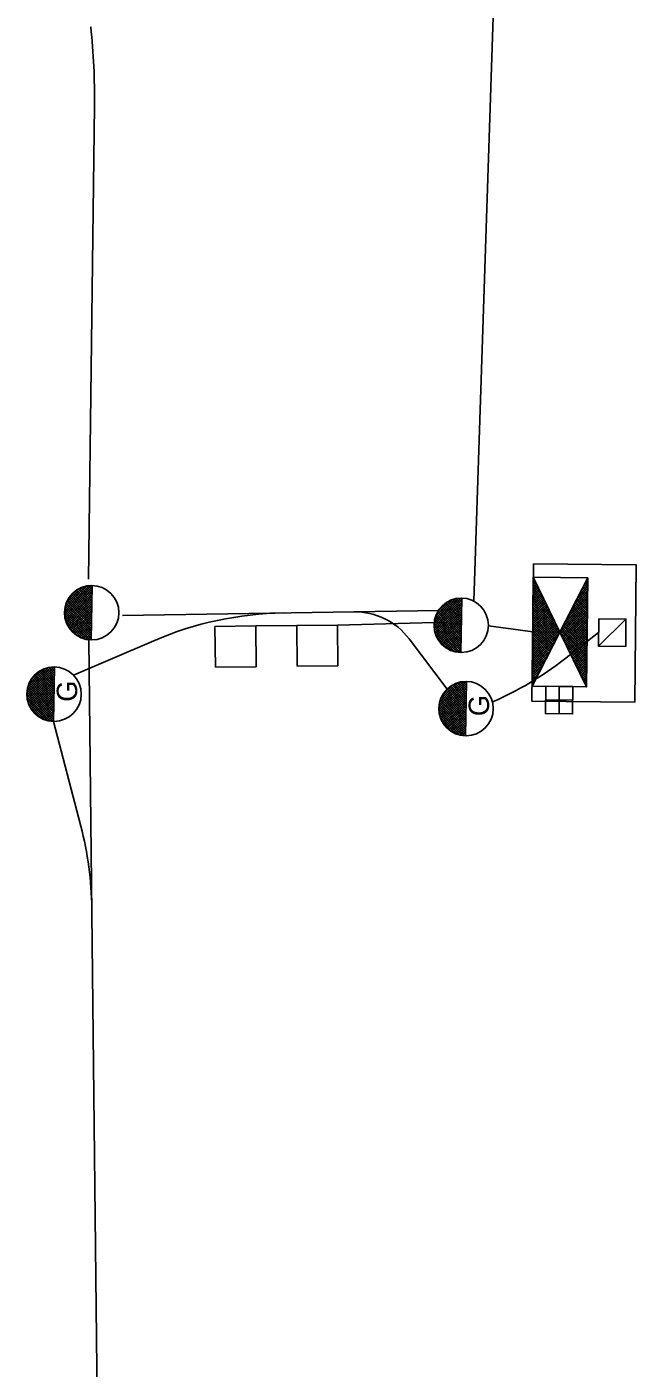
# Model space of a CAD drawing. Extents: x 584850 to 602551, y 145475 to 158627.
# Drawn here: x 585433.1 to 585522.7, y 152144.7 to 152341.8 of the extents above; entities that cross this region are included whole.
import ezdxf

# ---------------------------------------------------------------- set-up
doc = ezdxf.new("R2010")
doc.units = 0
doc.layers.add('Default', color=7, linetype='Continuous')

msp = doc.modelspace()

# ---------------------------------------------------------------- linework, layer by layer
at = {"layer": 'Default'}
for p, q in [((585498.86, 152257.42), (585505.09, 152448.58)), ((585442.22, 152260.66), (585443.08, 152330.19)), ((585442.66, 152259.72), (585438.68, 152255.88)), ((585442.29, 152259.7), (585438.71, 152256.26)), ((585441.88, 152259.64), (585438.77, 152256.64)), ((585441.62, 152259.58), (585442.72, 152258.44)), ((585441.9, 152259.64), (585442.72, 152258.78)), ((585442.18, 152259.69), (585442.73, 152259.12)), ((585442.5, 152259.71), (585442.74, 152259.46)), ((585442.59, 152251.73), (585442.74, 152259.73)), ((585442.7, 152259.73), (585442.74, 152259.68)), ((585508.06, 152259.94), (585507.56, 152259.45)), ((585508.17, 152259.71), (585507.56, 152259.11)), ((585507.73, 152260.62), (585507.57, 152260.47)), ((585507.84, 152260.39), (585507.57, 152260.13)), ((585508.17, 152259.71), (585507.57, 152260.32)), ((585507.95, 152260.16), (585507.57, 152259.79)), ((585508.5, 152259.03), (585507.57, 152259.98)), ((585508.84, 152258.34), (585507.57, 152259.64)), ((585507.62, 152260.85), (585507.58, 152260.81)), ((585507.84, 152260.39), (585507.58, 152260.66)), ((585515.57, 152259.89), (585514.61, 152258.96)), ((585515.57, 152260.23), (585514.96, 152259.63)), ((585515.56, 152259.02), (585514.96, 152259.63)), ((585515.56, 152259.36), (585515.08, 152259.86)), ((585515.57, 152259.7), (585515.19, 152260.08)), ((585515.58, 152260.57), (585515.31, 152260.31)), ((585515.57, 152260.04), (585515.31, 152260.31)), ((585515.58, 152260.38), (585515.42, 152260.53)), ((585515.58, 152260.72), (585515.54, 152260.76)), ((585442.74, 152259.46), (585438.68, 152255.56)), ((585442.73, 152259.12), (585438.7, 152255.24)), ((585442.72, 152258.78), (585438.75, 152254.96)), ((585442.72, 152258.44), (585438.81, 152254.68)), ((585442.71, 152258.11), (585438.9, 152254.43)), ((585441.42, 152259.53), (585438.93, 152257.13)), ((585442.7, 152257.77), (585438.99, 152254.19)), ((585439.17, 152257.63), (585442.63, 152254.03)), ((585440.8, 152259.27), (585439.22, 152257.74)), ((585439.28, 152257.86), (585442.64, 152254.37)), ((585439.43, 152258.06), (585442.65, 152254.71)), ((585439.57, 152258.25), (585442.65, 152255.05)), ((585439.72, 152258.44), (585442.66, 152255.39)), ((585439.9, 152258.6), (585442.67, 152255.73)), ((585440.08, 152258.76), (585442.67, 152256.07)), ((585440.26, 152258.92), (585442.68, 152256.41)), ((585440.46, 152259.05), (585442.69, 152256.75)), ((585440.67, 152259.19), (585442.69, 152257.09)), ((585440.89, 152259.3), (585442.7, 152257.43)), ((585441.13, 152259.41), (585442.7, 152257.77)), ((585441.36, 152259.51), (585442.71, 152258.11)), ((585496.99, 152257.87), (585493, 152254.04)), ((585497.06, 152257.61), (585493.01, 152253.71)), ((585496.62, 152257.85), (585493.04, 152254.41)), ((585496.21, 152257.79), (585493.1, 152254.79)), ((585495.75, 152257.68), (585493.26, 152255.28)), ((585495.69, 152257.66), (585497.04, 152256.26)), ((585495.95, 152257.73), (585497.04, 152256.6)), ((585496.22, 152257.79), (585497.05, 152256.93)), ((585496.51, 152257.84), (585497.06, 152257.27)), ((585496.82, 152257.86), (585497.06, 152257.61)), ((585496.92, 152249.88), (585497.07, 152257.88)), ((585497.02, 152257.88), (585497.07, 152257.83)), ((585508.95, 152258.12), (585507.53, 152256.74)), ((585509.06, 152257.89), (585507.53, 152256.4)), ((585509.17, 152257.66), (585507.53, 152256.06)), ((585508.61, 152258.8), (585507.54, 152257.75)), ((585508.73, 152258.57), (585507.54, 152257.41)), ((585508.84, 152258.34), (585507.54, 152257.07)), ((585510.83, 152254.25), (585507.54, 152257.61)), ((585508.39, 152259.25), (585507.55, 152258.43)), ((585508.5, 152259.03), (585507.55, 152258.09)), ((585509.83, 152256.3), (585507.55, 152258.63)), ((585510.16, 152255.61), (585507.55, 152258.29)), ((585510.49, 152254.93), (585507.55, 152257.95)), ((585508.28, 152259.48), (585507.56, 152258.77)), ((585509.17, 152257.66), (585507.56, 152259.3)), ((585509.5, 152256.98), (585507.56, 152258.96)), ((585515.55, 152257.86), (585512.53, 152254.91)), ((585515.55, 152258.2), (585512.88, 152255.58)), ((585515.56, 152258.54), (585513.23, 152256.26)), ((585515.56, 152258.88), (585513.57, 152256.93)), ((585515.56, 152259.22), (585513.92, 152257.61)), ((585515.53, 152255.96), (585513.92, 152257.61)), ((585515.53, 152256.3), (585514.03, 152257.83)), ((585515.53, 152256.64), (585514.15, 152258.06)), ((585515.57, 152259.56), (585514.27, 152258.28)), ((585515.54, 152256.98), (585514.27, 152258.28)), ((585515.54, 152257.32), (585514.38, 152258.51)), ((585515.55, 152257.66), (585514.5, 152258.73)), ((585515.55, 152258), (585514.61, 152258.96)), ((585515.55, 152258.34), (585514.73, 152259.18)), ((585515.56, 152258.68), (585514.84, 152259.41)), ((585438.68, 152255.72), (585442.52, 152251.74)), ((585438.69, 152256.06), (585442.6, 152252)), ((585438.73, 152256.36), (585442.6, 152252.34)), ((585438.78, 152256.66), (585442.61, 152252.68)), ((585438.86, 152256.91), (585442.62, 152253.01)), ((585438.94, 152257.17), (585442.62, 152253.35)), ((585439.05, 152257.41), (585442.63, 152253.69)), ((585442.7, 152257.43), (585439.09, 152253.95)), ((585442.69, 152257.09), (585439.21, 152253.74)), ((585442.69, 152256.75), (585439.34, 152253.52)), ((585442.68, 152256.41), (585439.48, 152253.33)), ((585442.67, 152256.07), (585439.63, 152253.14)), ((585442.67, 152255.73), (585439.79, 152252.96)), ((585493.66, 152256.03), (585447.2, 152255.34)), ((585497.06, 152257.27), (585493.03, 152253.39)), ((585497.05, 152256.93), (585493.08, 152253.11)), ((585497.04, 152256.6), (585493.14, 152252.83)), ((585497.04, 152256.26), (585493.22, 152252.58)), ((585497.03, 152255.92), (585493.31, 152252.34)), ((585493.49, 152255.79), (585496.96, 152252.18)), ((585495.13, 152257.42), (585493.55, 152255.9)), ((585493.61, 152256.01), (585496.97, 152252.52)), ((585493.75, 152256.21), (585496.97, 152252.86)), ((585493.9, 152256.4), (585496.98, 152253.2)), ((585494.05, 152256.59), (585496.99, 152253.54)), ((585494.23, 152256.75), (585496.99, 152253.88)), ((585494.4, 152256.91), (585497, 152254.22)), ((585494.59, 152257.07), (585497, 152254.56)), ((585494.79, 152257.2), (585497.01, 152254.9)), ((585495, 152257.34), (585497.02, 152255.24)), ((585495.22, 152257.45), (585497.02, 152255.58)), ((585495.45, 152257.56), (585497.03, 152255.92)), ((585509.83, 152256.3), (585507.5, 152254.02)), ((585509.94, 152256.07), (585507.5, 152253.68)), ((585510.05, 152255.84), (585507.5, 152253.34)), ((585509.5, 152256.98), (585507.51, 152255.04)), ((585509.61, 152256.75), (585507.51, 152254.7)), ((585509.72, 152256.52), (585507.51, 152254.36)), ((585509.28, 152257.43), (585507.52, 152255.72)), ((585509.39, 152257.21), (585507.52, 152255.38)), ((585511.14, 152252.21), (585507.52, 152255.91)), ((585511.37, 152252.66), (585507.53, 152256.59)), ((585511.26, 152252.43), (585507.53, 152256.25)), ((585511.16, 152253.57), (585507.54, 152257.27)), ((585511.49, 152252.88), (585507.54, 152256.93)), ((585515.54, 152256.84), (585511.49, 152252.88)), ((585515.53, 152256.5), (585511.6, 152252.66)), ((585515.53, 152256.16), (585511.71, 152252.43)), ((585515.53, 152255.82), (585511.82, 152252.2)), ((585515.54, 152257.18), (585511.84, 152253.56)), ((585515.54, 152257.52), (585512.18, 152254.23)), ((585515.5, 152253.25), (585512.99, 152255.81)), ((585515.5, 152253.59), (585513.11, 152256.03)), ((585515.5, 152253.93), (585513.22, 152256.26)), ((585515.51, 152254.27), (585513.34, 152256.48)), ((585515.51, 152254.61), (585513.46, 152256.71)), ((585515.52, 152254.95), (585513.57, 152256.93)), ((585515.52, 152255.28), (585513.69, 152257.16)), ((585515.52, 152255.62), (585513.8, 152257.38)), ((585438.69, 152255.36), (585442.15, 152251.77)), ((585438.76, 152254.94), (585441.74, 152251.85)), ((585438.88, 152254.47), (585441.26, 152252)), ((585439.15, 152253.84), (585440.64, 152252.3)), ((585442.66, 152255.39), (585439.96, 152252.79)), ((585442.65, 152255.05), (585440.15, 152252.64)), ((585442.65, 152254.71), (585440.33, 152252.48)), ((585442.64, 152254.37), (585440.54, 152252.35)), ((585442.63, 152254.03), (585440.76, 152252.23)), ((585442.63, 152253.69), (585440.98, 152252.11)), ((585460.79, 152253.72), (585466.79, 152253.78)), ((585460.79, 152253.72), (585460.86, 152247.72)), ((585466.79, 152253.78), (585472.8, 152253.85)), ((585466.86, 152247.78), (585466.79, 152253.78)), ((585472.8, 152253.85), (585478.8, 152253.91)), ((585472.8, 152253.85), (585472.86, 152247.85)), ((585478.8, 152253.91), (585494.84, 152254.36)), ((585478.86, 152247.91), (585478.8, 152253.91)), ((585493.01, 152254.21), (585496.92, 152250.15)), ((585493.01, 152253.87), (585496.84, 152249.89)), ((585493.06, 152254.51), (585496.93, 152250.49)), ((585493.1, 152254.81), (585496.93, 152250.83)), ((585493.19, 152255.06), (585496.94, 152251.17)), ((585493.27, 152255.32), (585496.95, 152251.5)), ((585493.37, 152255.56), (585496.95, 152251.84)), ((585497.02, 152255.58), (585493.41, 152252.1)), ((585497.02, 152255.24), (585493.54, 152251.89)), ((585497.01, 152254.9), (585493.66, 152251.68)), ((585497, 152254.56), (585493.8, 152251.48)), ((585497, 152254.22), (585493.96, 152251.29)), ((585496.99, 152253.88), (585494.12, 152251.11)), ((585507.49, 152252.93), (585500.99, 152253.81)), ((585511.05, 152253.79), (585507.46, 152250.29)), ((585510.72, 152254.48), (585507.47, 152251.31)), ((585510.83, 152254.25), (585507.47, 152250.97)), ((585510.94, 152254.02), (585507.47, 152250.63)), ((585510.38, 152255.16), (585507.48, 152252.32)), ((585510.49, 152254.93), (585507.48, 152251.98)), ((585510.61, 152254.7), (585507.48, 152251.64)), ((585510.16, 152255.61), (585507.49, 152253)), ((585510.27, 152255.39), (585507.49, 152252.66)), ((585510.45, 152250.86), (585507.5, 152253.87)), ((585510.8, 152251.53), (585507.51, 152254.89)), ((585510.68, 152251.31), (585507.51, 152254.55)), ((585510.56, 152251.08), (585507.51, 152254.21)), ((585511.03, 152251.98), (585507.52, 152255.57)), ((585510.91, 152251.76), (585507.52, 152255.23)), ((585515.52, 152255.48), (585511.93, 152251.97)), ((585515.46, 152250.19), (585511.95, 152253.78)), ((585515.52, 152255.14), (585512.04, 152251.75)), ((585515.47, 152250.53), (585512.07, 152254.01)), ((585515.51, 152254.8), (585512.15, 152251.52)), ((585515.47, 152250.87), (585512.18, 152254.23)), ((585515.51, 152254.47), (585512.26, 152251.29)), ((585515.47, 152251.21), (585512.3, 152254.46)), ((585515.51, 152254.13), (585512.37, 152251.06)), ((585515.48, 152251.55), (585512.42, 152254.68)), ((585515.5, 152253.79), (585512.49, 152250.84)), ((585515.48, 152251.89), (585512.53, 152254.91)), ((585515.49, 152252.23), (585512.65, 152255.13)), ((585515.49, 152252.57), (585512.76, 152255.36)), ((585515.49, 152252.91), (585512.88, 152255.58)), ((585517.16, 152250.82), (585521.2, 152254.78)), ((585442.62, 152253.35), (585441.23, 152252.01)), ((585442.62, 152253.01), (585441.48, 152251.92)), ((585442.61, 152252.68), (585441.75, 152251.85)), ((585442.6, 152252.34), (585442.04, 152251.79)), ((585442.6, 152252), (585442.34, 152251.75)), ((585442.59, 152251.73), (585442.59, 152251.73)), ((585442.59, 152251.73), (585442.59, 152251.73)), ((585494.91, 152244.51), (585489.33, 152251.88)), ((585493.01, 152253.51), (585496.47, 152249.92)), ((585493.08, 152253.09), (585496.06, 152250)), ((585493.21, 152252.62), (585495.59, 152250.15)), ((585493.48, 152251.99), (585494.97, 152250.45)), ((585496.99, 152253.54), (585494.29, 152250.94)), ((585496.98, 152253.2), (585494.48, 152250.79)), ((585496.97, 152252.86), (585494.66, 152250.63)), ((585496.97, 152252.52), (585494.87, 152250.5)), ((585496.96, 152252.18), (585495.09, 152250.38)), ((585496.95, 152251.84), (585495.31, 152250.26)), ((585511.14, 152252.21), (585507.44, 152248.59)), ((585511.27, 152253.34), (585507.45, 152249.61)), ((585511.38, 152253.11), (585507.45, 152249.27)), ((585511.49, 152252.88), (585507.45, 152248.93)), ((585511.16, 152253.57), (585507.46, 152249.95)), ((585509.87, 152249.73), (585507.48, 152252.18)), ((585509.76, 152249.51), (585507.48, 152251.84)), ((585510.22, 152250.41), (585507.49, 152253.19)), ((585510.1, 152250.18), (585507.49, 152252.85)), ((585509.99, 152249.96), (585507.49, 152252.52)), ((585510.33, 152250.63), (585507.5, 152253.53)), ((585515.45, 152248.84), (585511.49, 152252.88)), ((585515.45, 152249.18), (585511.61, 152253.11)), ((585515.46, 152249.51), (585511.72, 152253.33)), ((585515.44, 152248.5), (585511.82, 152252.2)), ((585515.46, 152249.85), (585511.84, 152253.56)), ((585517.18, 152252.82), (585512.17, 152248.92)), ((585515.5, 152253.45), (585512.6, 152250.61)), ((585515.5, 152253.11), (585512.71, 152250.38)), ((585515.49, 152252.77), (585512.82, 152250.15)), ((585515.49, 152252.43), (585512.93, 152249.93)), ((585515.48, 152252.09), (585513.04, 152249.7)), ((585515.48, 152251.75), (585513.15, 152249.47)), ((585440.02, 152246.53), (585451.82, 152251.61)), ((585442.26, 152251.68), (585445.51, 151951.65)), ((585496.95, 152251.5), (585495.55, 152250.16)), ((585496.94, 152251.17), (585495.8, 152250.07)), ((585496.93, 152250.83), (585496.07, 152250)), ((585496.93, 152250.49), (585496.36, 152249.94)), ((585496.92, 152250.15), (585496.66, 152249.9)), ((585496.92, 152249.88), (585496.92, 152249.88)), ((585496.92, 152249.88), (585496.92, 152249.88)), ((585510.45, 152250.86), (585507.43, 152247.91)), ((585510.1, 152250.18), (585507.43, 152247.57)), ((585510.8, 152251.53), (585507.44, 152248.25)), ((585509.29, 152248.61), (585507.46, 152250.48)), ((585509.18, 152248.38), (585507.46, 152250.14)), ((585509.06, 152248.16), (585507.46, 152249.8)), ((585509.52, 152249.06), (585507.47, 152251.16)), ((585509.41, 152248.83), (585507.47, 152250.82)), ((585509.64, 152249.28), (585507.48, 152251.5)), ((585515.44, 152248.16), (585512.15, 152251.52)), ((585515.44, 152247.82), (585512.49, 152250.84)), ((585515.43, 152247.48), (585512.82, 152250.15)), ((585515.48, 152251.41), (585513.26, 152249.24)), ((585515.47, 152251.07), (585513.37, 152249.02)), ((585515.47, 152250.73), (585513.48, 152248.79)), ((585515.47, 152250.39), (585513.59, 152248.56)), ((585515.46, 152250.05), (585513.7, 152248.33)), ((585515.46, 152249.71), (585513.81, 152248.11)), ((585437.13, 152247.74), (585433.15, 152243.91)), ((585437.06, 152239.75), (585437.21, 152247.75)), ((585437.17, 152247.75), (585437.21, 152247.71)), ((585460.86, 152247.72), (585466.86, 152247.78)), ((585472.86, 152247.85), (585478.86, 152247.91)), ((585509.41, 152248.84), (585507.42, 152246.89)), ((585509.06, 152248.16), (585507.42, 152246.55)), ((585509.76, 152249.51), (585507.43, 152247.23)), ((585508.37, 152246.81), (585507.43, 152247.76)), ((585508.71, 152247.48), (585507.44, 152248.78)), ((585508.6, 152247.26), (585507.44, 152248.44)), ((585508.48, 152247.03), (585507.44, 152248.1)), ((585508.95, 152247.93), (585507.45, 152249.46)), ((585508.83, 152247.71), (585507.45, 152249.12)), ((585515.43, 152247.14), (585513.15, 152249.47)), ((585515.43, 152246.8), (585513.48, 152248.79)), ((585515.42, 152246.46), (585513.81, 152248.1)), ((585515.45, 152249.37), (585513.92, 152247.88)), ((585515.45, 152249.04), (585514.03, 152247.65)), ((585515.45, 152248.7), (585514.14, 152247.42)), ((585515.44, 152248.36), (585514.26, 152247.2)), ((585515.44, 152248.02), (585514.37, 152246.97)), ((585437.21, 152247.48), (585433.16, 152243.58)), ((585437.2, 152247.14), (585433.17, 152243.26)), ((585436.76, 152247.72), (585433.19, 152244.28)), ((585437.2, 152246.8), (585433.23, 152242.98)), ((585436.36, 152247.66), (585433.24, 152244.67)), ((585437.19, 152246.47), (585433.28, 152242.7)), ((585437.18, 152246.13), (585433.37, 152242.45)), ((585435.89, 152247.55), (585433.4, 152245.15)), ((585437.18, 152245.79), (585433.46, 152242.21)), ((585435.28, 152247.29), (585433.7, 152245.77)), ((585433.76, 152245.88), (585437.11, 152242.39)), ((585433.9, 152246.08), (585437.12, 152242.73)), ((585434.05, 152246.27), (585437.13, 152243.07)), ((585434.2, 152246.46), (585437.13, 152243.41)), ((585434.37, 152246.62), (585437.14, 152243.75)), ((585434.55, 152246.79), (585437.14, 152244.09)), ((585434.73, 152246.94), (585437.15, 152244.43)), ((585434.94, 152247.07), (585437.16, 152244.77)), ((585435.14, 152247.21), (585437.16, 152245.11)), ((585435.36, 152247.33), (585437.17, 152245.45)), ((585435.6, 152247.43), (585437.18, 152245.79)), ((585435.83, 152247.53), (585437.18, 152246.13)), ((585436.1, 152247.6), (585437.19, 152246.47)), ((585436.37, 152247.66), (585437.2, 152246.8)), ((585436.65, 152247.71), (585437.2, 152247.14)), ((585436.97, 152247.73), (585437.21, 152247.48)), ((585508.37, 152246.81), (585507.41, 152245.88)), ((585508.02, 152246.14), (585507.41, 152245.54)), ((585507.79, 152245.68), (585507.41, 152246.07)), ((585508.72, 152247.49), (585507.42, 152246.21)), ((585508.02, 152246.13), (585507.42, 152246.75)), ((585507.9, 152245.91), (585507.42, 152246.41)), ((585508.25, 152246.58), (585507.43, 152247.42)), ((585508.14, 152246.36), (585507.43, 152247.08)), ((585515.42, 152246.12), (585514.15, 152247.42)), ((585515.43, 152247.68), (585514.48, 152246.74)), ((585515.41, 152245.78), (585514.48, 152246.74)), ((585515.43, 152247.34), (585514.59, 152246.51)), ((585515.43, 152247), (585514.7, 152246.29)), ((585515.42, 152246.66), (585514.81, 152246.06)), ((585515.41, 152245.44), (585514.81, 152246.06)), ((585515.42, 152246.32), (585514.92, 152245.83)), ((585515.42, 152245.98), (585515.03, 152245.6)), ((585433.16, 152244.08), (585437.07, 152240.02)), ((585433.2, 152244.38), (585437.07, 152240.36)), ((585433.25, 152244.68), (585437.08, 152240.7)), ((585433.33, 152244.94), (585437.09, 152241.04)), ((585433.42, 152245.19), (585437.09, 152241.38)), ((585433.52, 152245.43), (585437.1, 152241.71)), ((585437.17, 152245.45), (585433.56, 152241.97)), ((585433.64, 152245.66), (585437.11, 152242.05)), ((585437.16, 152245.11), (585433.69, 152241.76)), ((585437.16, 152244.77), (585433.81, 152241.55)), ((585437.15, 152244.43), (585433.95, 152241.35)), ((585437.14, 152244.09), (585434.11, 152241.16)), ((585441.05, 152244.74), (585440.95, 152244.69)), ((585497.68, 152245.62), (585493.7, 152241.78)), ((585497.76, 152245.36), (585493.7, 152241.46)), ((585497.75, 152245.02), (585493.72, 152241.14)), ((585497.31, 152245.6), (585493.73, 152242.15)), ((585497.74, 152244.68), (585493.77, 152240.86)), ((585496.9, 152245.54), (585493.79, 152242.54)), ((585497.74, 152244.34), (585493.83, 152240.58)), ((585497.73, 152244), (585493.92, 152240.33)), ((585496.44, 152245.43), (585493.95, 152243.03)), ((585495.82, 152245.17), (585494.24, 152243.64)), ((585494.45, 152243.95), (585497.67, 152240.61)), ((585494.59, 152244.15), (585497.67, 152240.95)), ((585494.74, 152244.34), (585497.68, 152241.29)), ((585494.92, 152244.5), (585497.69, 152241.63)), ((585495.1, 152244.66), (585497.69, 152241.97)), ((585495.28, 152244.82), (585497.7, 152242.31)), ((585495.48, 152244.95), (585497.7, 152242.65)), ((585495.69, 152245.08), (585497.71, 152242.99)), ((585495.91, 152245.2), (585497.72, 152243.32)), ((585496.14, 152245.3), (585497.72, 152243.66)), ((585496.38, 152245.41), (585497.73, 152244)), ((585496.64, 152245.48), (585497.74, 152244.34)), ((585496.91, 152245.54), (585497.74, 152244.68)), ((585497.2, 152245.59), (585497.75, 152245.02)), ((585497.51, 152245.61), (585497.76, 152245.36)), ((585497.61, 152237.63), (585497.76, 152245.63)), ((585497.72, 152245.63), (585497.76, 152245.58)), ((585507.68, 152245.46), (585507.4, 152245.2)), ((585507.44, 152245.01), (585507.4, 152245.05)), ((585507.67, 152245.46), (585507.41, 152245.73)), ((585507.56, 152245.23), (585507.41, 152245.39)), ((585511.4, 152244.89), (585511.36, 152240.89)), ((585515.41, 152245.64), (585515.14, 152245.38)), ((585515.41, 152245.1), (585515.14, 152245.37)), ((585515.41, 152245.3), (585515.25, 152245.15)), ((585515.4, 152244.96), (585515.36, 152244.92)), ((585433.15, 152243.74), (585436.99, 152239.76)), ((585433.16, 152243.38), (585436.62, 152239.79)), ((585433.23, 152242.96), (585436.21, 152239.87)), ((585433.35, 152242.49), (585435.73, 152240.02)), ((585433.62, 152241.86), (585435.11, 152240.32)), ((585437.14, 152243.75), (585434.26, 152240.98)), ((585437.13, 152243.41), (585434.44, 152240.82)), ((585437.13, 152243.07), (585434.62, 152240.66)), ((585437.12, 152242.73), (585434.81, 152240.5)), ((585437.11, 152242.39), (585435.02, 152240.37)), ((585437.11, 152242.05), (585435.23, 152240.25)), ((585493.7, 152241.96), (585497.62, 152237.9)), ((585493.75, 152242.25), (585497.62, 152238.23)), ((585493.79, 152242.55), (585497.63, 152238.57)), ((585493.88, 152242.81), (585497.63, 152238.91)), ((585493.96, 152243.07), (585497.64, 152239.25)), ((585497.72, 152243.66), (585494.01, 152240.09)), ((585494.07, 152243.31), (585497.65, 152239.59)), ((585497.72, 152243.32), (585494.11, 152239.85)), ((585494.18, 152243.53), (585497.65, 152239.93)), ((585497.71, 152242.99), (585494.23, 152239.64)), ((585494.3, 152243.76), (585497.66, 152240.27)), ((585497.7, 152242.65), (585494.36, 152239.42)), ((585497.7, 152242.31), (585494.5, 152239.22)), ((585497.69, 152241.97), (585494.65, 152239.04)), ((585501.59, 152242.61), (585501.49, 152242.57)), ((585513.38, 152242.86), (585509.38, 152242.91)), ((585437.1, 152241.71), (585435.45, 152240.13)), ((585437.09, 152241.38), (585435.7, 152240.03)), ((585437.09, 152241.04), (585435.95, 152239.94)), ((585437.08, 152240.7), (585436.22, 152239.87)), ((585437.07, 152240.36), (585436.51, 152239.81)), ((585437.07, 152240.02), (585436.81, 152239.77)), ((585493.7, 152241.62), (585497.53, 152237.63)), ((585493.71, 152241.26), (585497.17, 152237.67)), ((585493.78, 152240.84), (585496.76, 152237.75)), ((585493.9, 152240.37), (585496.28, 152237.9)), ((585497.69, 152241.63), (585494.81, 152238.86)), ((585497.68, 152241.29), (585494.98, 152238.69)), ((585497.67, 152240.95), (585495.17, 152238.54)), ((585497.67, 152240.61), (585495.35, 152238.38)), ((585497.66, 152240.27), (585495.56, 152238.25)), ((585497.65, 152239.93), (585495.78, 152238.13)), ((585437.06, 152239.75), (585441.07, 152224.37)), ((585437.06, 152239.75), (585437.06, 152239.75)), ((585437.06, 152239.75), (585437.06, 152239.75)), ((585494.17, 152239.74), (585495.66, 152238.2)), ((585497.65, 152239.59), (585496, 152238)), ((585497.64, 152239.25), (585496.25, 152237.91)), ((585497.63, 152238.91), (585496.5, 152237.82)), ((585497.63, 152238.57), (585496.77, 152237.75)), ((585497.62, 152238.23), (585497.06, 152237.69)), ((585497.62, 152237.9), (585497.36, 152237.64)), ((585497.61, 152237.63), (585497.61, 152237.63)), ((585497.61, 152237.63), (585497.61, 152237.63))]:
    msp.add_line(p, q, dxfattribs=at)
for points in [[(585507.6, 152262.93), (585507.38, 152242.73), (585522.48, 152242.57), (585522.7, 152262.76)], [(585507.58, 152260.93), (585507.4, 152244.93), (585515.4, 152244.84), (585515.58, 152260.84)], [(585507.58, 152260.93), (585511.49, 152252.88), (585507.4, 152244.93)], [(585515.58, 152260.84), (585515.4, 152244.83), (585511.49, 152252.88)], [(585517.2, 152254.82), (585517.16, 152250.82), (585521.16, 152250.78), (585521.2, 152254.78)], [(585509.4, 152244.91), (585509.36, 152240.91), (585513.36, 152240.86), (585513.4, 152244.86)]]:
    msp.add_lwpolyline(points, close=True, dxfattribs=at)
for points in [[(585521.2, 152254.78), (585517.16, 152250.82), (585521.16, 152250.78), (585521.2, 152254.78)], [(585521.16, 152250.78), (585521.2, 152254.78), (585517.16, 152250.82), (585521.16, 152250.78)], [(585521.2, 152254.78), (585517.16, 152250.82), (585521.16, 152250.78), (585521.2, 152254.78)], [(585521.2, 152254.78), (585517.16, 152250.82), (585521.16, 152250.78), (585521.2, 152254.78)]]:
    msp.add_lwpolyline(points, dxfattribs=at)
for centre in [(585442.67, 152255.73), (585496.99, 152253.88), (585437.14, 152243.75), (585497.69, 152241.63)]:
    msp.add_circle(centre, 4, dxfattribs=at)
for centre, radius, start, end in [((585343.09, 152331.41), 100, 359.297, 5.9743), ((585442.67, 152255.73), 4, 88.9257, 268.9257), ((585496.99, 152253.88), 4, 88.9257, 268.9257), ((585471.62, 152205.7), 50, 90.8551, 113.3203), ((585481.36, 152245.85), 10, 37.1124, 90.8551), ((585437.14, 152243.75), 4, 88.9257, 268.9257), ((585481.46, 152288.38), 50, 293.7495, 307.8903), ((585497.69, 152241.63), 4, 88.9257, 268.9257), ((585392.69, 152211.75), 50, 0.6202, 14.618)]:
    msp.add_arc(centre, radius, start, end, dxfattribs=at)

# ---------------------------------------------------------------- texts
for p in [(585440.52, 152242.62), (585501.06, 152240.5)]:
    msp.add_text('G', height=3, rotation=89.3623, dxfattribs=at).set_placement(p)

doc.saveas('drawing.dxf')
